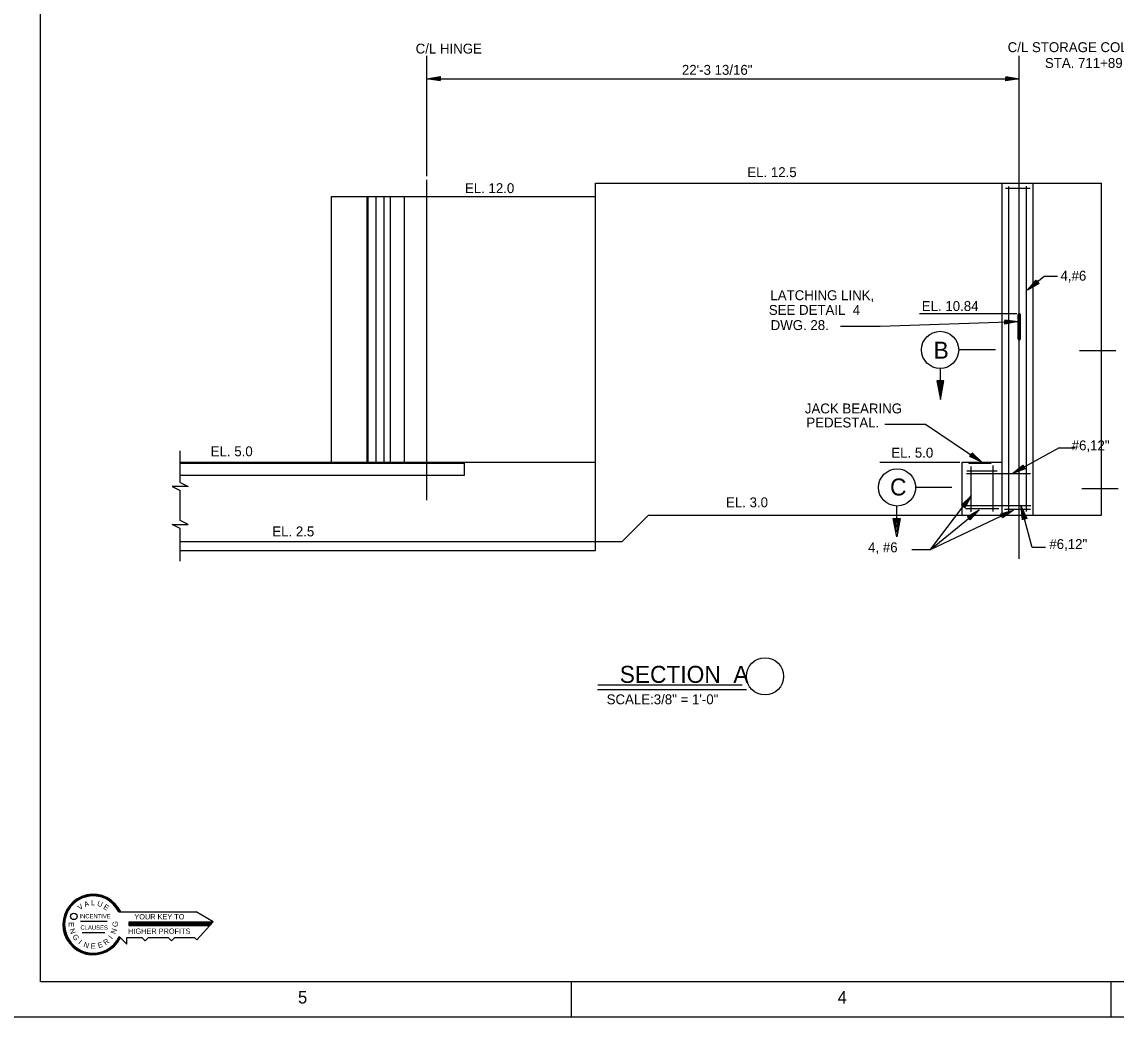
# Model space of a CAD drawing. Extents: x -48 to 108, y -5 to 100.
# Drawn here: x 4.59 to 45.82, y 1.29 to 38.78 of the extents above; entities that cross this region are included whole.
import ezdxf

# ---------------------------------------------------------------- set-up
doc = ezdxf.new("R2010")
doc.units = 0
for name, color, linetype in [('Level 1', 7, 'Continuous'), ('Level 13', 7, 'Continuous'), ('Level 2', 7, 'Continuous'), ('Level 22', 7, 'Continuous'), ('Level 25', 7, 'Continuous'), ('Level 3', 7, 'Continuous'), ('Level 50', 7, 'Continuous')]:
    doc.layers.add(name, color=color, linetype=linetype)

msp = doc.modelspace()

# ---------------------------------------------------------------- linework, layer by layer
at = {"layer": 'Level 1'}
for p, q in [((8.244, 5.253), (11.158, 5.253)), ((11.794, 4.877), (11.158, 5.253)), ((6.804, 4.903), (7.802, 4.903)), ((11.786, 4.867), (8.614, 4.867)), ((8.614, 4.867), (8.614, 4.743)), ((11.754, 4.833), (8.614, 4.833)), ((11.726, 4.801), (8.614, 4.801)), ((11.696, 4.767), (8.614, 4.767)), ((8.614, 4.743), (11.674, 4.743)), ((11.794, 4.877), (11.188, 4.199)), ((6.856, 4.481), (7.72, 4.481)), ((8.258, 4.333), (8.548, 4.043)), ((8.548, 4.043), (8.548, 4.293)), ((8.548, 4.293), (9.11, 4.293)), ((9.11, 4.293), (9.234, 4.169)), ((9.234, 4.169), (9.358, 4.293)), ((9.358, 4.293), (10.102, 4.293)), ((10.102, 4.293), (10.226, 4.169)), ((10.226, 4.169), (10.35, 4.293)), ((10.35, 4.293), (11.094, 4.293)), ((11.094, 4.293), (11.188, 4.199)), ((25.292, 2.625), (25.292, 1.292)), ((45.625, 2.625), (45.625, 1.292))]:
    msp.add_line(p, q, dxfattribs=at)
for points in [[(1.292, 75.958), (107.958, 75.958), (107.958, 1.292), (1.292, 1.292)], [(5.292, 74.625), (106.625, 74.625), (106.625, 2.625), (5.292, 2.625)]]:
    msp.add_lwpolyline(points, close=True, dxfattribs=at)
msp.add_circle((6.545, 5.088), 0.123, dxfattribs=at)
for radius, start, end in [(1.14, 24.569, 334.4243), (1.109, 25.3095, 334.4522), (1.078, 26.0896, 335.5943)]:
    msp.add_arc((7.276, 4.779), radius, start, end, dxfattribs=at)
at = {"layer": 'Level 13'}
for points in [[(10.55, 21.433), (10.85, 21.284), (10.251, 21.284), (10.55, 21.134)], [(10.55, 19.704), (10.25, 19.853), (10.85, 19.853), (10.55, 20.003)]]:
    msp.add_lwpolyline(points, dxfattribs=at)
at = {"layer": 'Level 2'}
msp.add_line((36.925, 27.326), (42.126, 27.498), dxfattribs=at)
for centre, start, end in [((42.168, 27.756), 0, 180), ((42.168, 26.839), 179.2231, 10.3048)]:
    msp.add_arc(centre, 0.0417, start, end, dxfattribs=at)
at = {"layer": 'Level 22'}
for p, q in [((19.85, 32.972), (19.85, 37.511)), ((42.168, 32.638), (42.168, 37.511)), ((19.85, 36.641), (42.168, 36.641)), ((19.85, 20.764), (19.85, 32.838)), ((26.204, 18.871), (26.204, 32.704)), ((26.204, 32.704), (45.272, 32.704)), ((41.522, 20.204), (41.522, 32.704)), ((41.772, 20.344), (41.772, 32.588)), ((42.168, 18.562), (42.168, 32.638)), ((42.439, 20.335), (42.439, 32.594)), ((42.689, 20.204), (42.689, 32.704)), ((45.272, 20.204), (45.272, 32.704)), ((16.262, 32.204), (26.204, 32.204)), ((16.262, 22.204), (16.262, 32.204)), ((17.6, 22.204), (17.6, 32.204)), ((17.642, 22.204), (17.642, 32.204)), ((17.934, 22.204), (17.934, 32.204)), ((18.246, 22.204), (18.246, 32.204)), ((18.475, 22.204), (18.475, 32.204)), ((19.012, 22.204), (19.012, 32.204)), ((41.651, 32.515), (42.586, 32.515)), ((38.407, 27.798), (42.084, 27.798)), ((42.126, 26.839), (42.126, 27.756)), ((42.21, 26.839), (42.21, 27.756)), ((35.438, 27.326), (36.925, 27.326)), ((37.1, 23.629), (38.632, 23.629)), ((38.632, 23.629), (40.761, 22.204)), ((43.668, 22.735), (41.913, 21.774)), ((43.668, 22.735), (44.274, 22.735)), ((10.55, 21.433), (10.55, 22.619)), ((10.55, 22.204), (26.204, 22.204)), ((10.55, 22.162), (21.272, 22.162)), ((21.272, 21.704), (21.272, 22.204)), ((36.91, 22.204), (39.936, 22.204)), ((40.022, 20.204), (40.022, 22.204)), ((40.022, 22.204), (41.522, 22.204)), ((40.19, 21.871), (41.336, 21.871)), ((40.272, 22.162), (40.272, 22.204)), ((40.272, 22.162), (41.105, 22.162)), ((40.355, 20.326), (40.355, 22.035)), ((41.105, 22.162), (41.105, 22.204)), ((41.189, 20.344), (41.189, 22.073)), ((10.55, 21.704), (21.272, 21.704)), ((40.181, 21.774), (42.587, 21.774)), ((10.55, 20.003), (10.55, 21.134)), ((38.82, 18.914), (40.355, 20.925)), ((27.204, 19.204), (28.204, 20.204)), ((28.204, 20.204), (45.272, 20.204)), ((40.129, 20.567), (42.606, 20.567)), ((40.147, 20.454), (41.394, 20.454)), ((41.618, 20.433), (42.596, 20.433)), ((10.55, 18.47), (10.55, 19.704)), ((10.55, 19.204), (27.204, 19.204)), ((10.55, 18.871), (26.204, 18.871)), ((38.117, 18.914), (38.82, 18.914))]:
    msp.add_line(p, q, dxfattribs=at)
at = {"layer": 'Level 25'}
for p, q in [((26.277, 13.635), (31.89, 13.635)), ((26.295, 13.806), (31.732, 13.806))]:
    msp.add_line(p, q, dxfattribs=at)
at = {"layer": 'Level 3'}
for p, q in [((42.474, 28.678), (42.474, 28.678)), ((42.582, 28.765), (42.582, 28.765)), ((41.276, 26.428), (39.899, 26.428)), ((44.436, 26.405), (45.813, 26.405)), ((39.2, 25.262), (39.2, 25.728)), ((39.629, 21.246), (38.252, 21.246)), ((44.523, 21.205), (45.9, 21.205)), ((37.553, 20.079), (37.553, 20.546)), ((38.82, 18.914), (40.655, 20.407)), ((38.82, 18.914), (41.957, 20.389)), ((40.547, 20.319), (40.547, 20.319)), ((40.655, 20.407), (40.655, 20.407)), ((41.832, 20.33), (41.832, 20.33)), ((41.957, 20.389), (41.957, 20.389)), ((42.242, 20.531), (42.242, 20.531)), ((42.279, 20.398), (42.279, 20.398))]:
    msp.add_line(p, q, dxfattribs=at)
for points in [[(43.607, 29.19), (43.108, 29.19), (42.474, 28.678)], [(42.914, 28.927), (42.474, 28.678), (42.81, 29.055), (42.899, 28.946), (42.582, 28.765), (42.81, 29.021), (42.867, 28.951), (42.686, 28.849), (42.81, 28.987), (42.834, 28.958), (42.794, 28.936)], [(39.102, 25.262), (39.067, 25.262), (39.2, 24.562), (39.331, 25.262), (39.102, 25.262), (39.198, 24.74), (39.291, 25.228), (39.14, 25.228), (39.198, 24.916), (39.25, 25.195), (39.18, 25.195), (39.198, 25.095), (39.21, 25.161)], [(40.216, 20.156), (40.655, 20.407), (40.32, 20.028), (40.231, 20.137), (40.547, 20.319), (40.32, 20.062), (40.263, 20.132), (40.444, 20.235), (40.32, 20.096), (40.296, 20.125), (40.336, 20.147)], [(41.471, 20.251), (41.957, 20.389), (41.541, 20.102), (41.481, 20.23), (41.832, 20.33), (41.549, 20.135), (41.51, 20.217), (41.711, 20.273), (41.557, 20.168), (41.541, 20.202), (41.585, 20.214)], [(43.161, 18.988), (42.662, 18.988), (42.242, 20.531)], [(42.293, 20.029), (42.242, 20.531), (42.453, 20.072), (42.316, 20.035), (42.279, 20.398), (42.422, 20.086), (42.334, 20.062), (42.314, 20.269), (42.39, 20.099), (42.354, 20.089), (42.35, 20.135)], [(37.651, 20.079), (37.686, 20.079), (37.553, 19.379), (37.423, 20.079), (37.651, 20.079), (37.556, 19.558), (37.462, 20.045), (37.613, 20.045), (37.556, 19.734), (37.503, 20.013), (37.573, 20.013), (37.556, 19.912), (37.543, 19.979)]]:
    msp.add_lwpolyline(points, dxfattribs=at)
for centre in [(39.187, 26.428), (37.567, 21.246), (32.59, 14.128)]:
    msp.add_circle(centre, 0.7, dxfattribs=at)
at = {"layer": 'Level 50'}
for p, q in [((19.85, 36.641), (19.85, 36.641)), ((19.85, 36.641), (19.85, 36.641)), ((19.989, 36.641), (19.989, 36.641)), ((19.989, 36.641), (19.989, 36.641)), ((42.029, 36.641), (42.029, 36.641)), ((42.168, 36.641), (42.168, 36.641)), ((41.988, 27.494), (41.988, 27.494)), ((42.126, 27.498), (42.126, 27.498)), ((40.646, 22.281), (40.646, 22.281)), ((40.761, 22.204), (40.761, 22.204)), ((41.913, 21.774), (41.913, 21.774)), ((42.034, 21.841), (42.034, 21.841)), ((40.271, 20.815), (40.271, 20.815)), ((40.355, 20.925), (40.355, 20.925))]:
    msp.add_line(p, q, dxfattribs=at)
for points in [[(20.349, 36.558), (19.85, 36.641), (20.349, 36.723), (20.349, 36.582), (19.989, 36.641), (20.328, 36.697), (20.328, 36.606), (20.122, 36.641), (20.306, 36.67), (20.306, 36.633), (20.261, 36.641)], [(20.349, 36.558), (19.85, 36.641), (20.349, 36.723), (20.349, 36.582), (19.989, 36.641), (20.328, 36.697), (20.328, 36.606), (20.122, 36.641), (20.306, 36.67), (20.306, 36.633), (20.261, 36.641)], [(41.669, 36.723), (42.168, 36.641), (41.669, 36.558), (41.669, 36.699), (42.029, 36.641), (41.691, 36.585), (41.691, 36.675), (41.896, 36.641), (41.712, 36.611), (41.712, 36.649), (41.757, 36.641)], [(41.625, 27.565), (42.126, 27.498), (41.631, 27.399), (41.626, 27.541), (41.988, 27.494), (41.651, 27.427), (41.648, 27.517), (41.854, 27.489), (41.671, 27.454), (41.67, 27.491), (41.716, 27.485)], [(40.393, 22.55), (40.761, 22.204), (40.301, 22.413), (40.379, 22.53), (40.646, 22.281), (40.333, 22.423), (40.384, 22.498), (40.535, 22.355), (40.366, 22.433), (40.387, 22.464), (40.42, 22.432)], [(42.39, 21.941), (41.913, 21.774), (42.31, 22.086), (42.378, 21.962), (42.034, 21.841), (42.304, 22.052), (42.348, 21.973), (42.151, 21.905), (42.299, 22.019), (42.317, 21.986), (42.273, 21.971)], [(39.987, 20.579), (40.355, 20.925), (40.119, 20.478), (40.006, 20.564), (40.271, 20.815), (40.11, 20.511), (40.038, 20.566), (40.19, 20.709), (40.102, 20.545), (40.072, 20.567), (40.106, 20.598)]]:
    msp.add_lwpolyline(points, dxfattribs=at)

# ---------------------------------------------------------------- texts
at = {"layer": 'Level 1'}
for s, rotation, p in [('V', 35.9204, (6.778, 5.307)), ('A', 18.0731, (6.964, 5.435)), ('U', 342.1107, (7.41, 5.493)), ('E', 323.9298, (7.638, 5.403)), ('E', 270, (6.354, 4.867)), ('N', 288.0821, (6.376, 4.595)), ('N', 71.9179, (8.118, 4.405)), ('G', 90, (8.206, 4.687)), ('G', 306.0537, (6.478, 4.323)), ('I', 323.5836, (6.7, 4.069)), ('N', 341.9179, (6.896, 3.943)), ('E', 18.2241, (7.484, 3.887)), ('R', 36.2206, (7.746, 3.989)), ('I', 53.5836, (7.994, 4.209))]:
    msp.add_text(s, height=0.2, rotation=rotation, dxfattribs=at).set_placement(p)
for s, height, p in [('L', 0.2, (7.194, 5.501)), ('INCENTIVE', 0.16, (6.76, 5.013)), ('YOUR KEY TO', 0.2, (8.828, 4.973)), ('CLAUSES', 0.16, (6.798, 4.585)), ('HIGHER PROFITS', 0.2, (8.594, 4.429)), ('E', 0.2, (7.19, 3.865)), ('5', 0.467, (14.994, 1.804)), ('4', 0.467, (35.327, 1.803))]:
    msp.add_text(s, height=height, dxfattribs=at).set_placement(p)
at = {"layer": 'Level 2'}
for s, p in [('B', (38.942, 26.097)), ('C', (37.302, 20.943)), ('SECTION  A', (27.117, 13.884))]:
    msp.add_text(s, height=0.64, dxfattribs=at).set_placement(p)
at = {"layer": 'Level 25'}
for s, height, p in [('C/L HINGE', 0.3733, (19.427, 37.591)), ('C/L STORAGE COLUMN LATCH', 0.37333, (41.733, 37.645)), ('22\'-3 13/16"', 0.37333, (29.458, 36.791)), ('STA. 711+89.69 W/L', 0.37333, (43.136, 37.051)), ('EL. 12.5', 0.3733, (31.923, 32.936)), ('EL. 12.0', 0.3733, (21.283, 32.334)), ('4,#6', 0.3733, (43.723, 29.035)), ('LATCHING LINK,', 0.37333, (32.793, 28.3)), ('SEE DETAIL  4', 0.37333, (32.734, 27.747)), ('EL. 10.84', 0.3733, (38.497, 27.893)), ('DWG. 28.', 0.3733, (32.803, 27.175)), ('JACK BEARING', 0.37333, (34.091, 24.035)), ('PEDESTAL.', 0.3733, (34.148, 23.505)), ('EL. 5.0', 0.3733, (11.706, 22.42)), ('EL. 5.0', 0.3733, (37.347, 22.368)), ('#6,12"', 0.3733, (44.145, 22.644)), ('EL. 3.0', 0.3733, (31.121, 20.499)), ('EL. 2.5', 0.3733, (14.025, 19.402)), ('4, #6', 0.3733, (36.475, 18.802)), ('#6,12"', 0.3733, (43.303, 18.926)), ('SCALE:3/8" = 1\'-0"', 0.37333, (26.623, 13.077))]:
    msp.add_text(s, height=height, dxfattribs=at).set_placement(p)

doc.saveas('drawing.dxf')
